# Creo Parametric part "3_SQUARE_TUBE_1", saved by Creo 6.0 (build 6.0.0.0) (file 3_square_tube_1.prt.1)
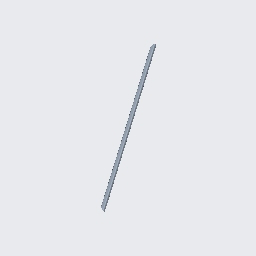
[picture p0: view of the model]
Units: Custom; MM, KILOGRAM, SECS
Materials in the file: STEEL

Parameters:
  BUW_NAME = "SQUARE TUBE"
  BUW_TYPE = "DIN EN 10219"
  BUW_SIZE = "25x25x3.0"
  BUW_LENGTH_STR = "1235"
  PTC_MATERIAL_NAME = "STEEL"
  BUW_PROFIL_TYPE = "square_tube"
  BUW_PROFILE_PATH = "parts//profiles/steel_beams_mm/"
  BUW_PROFILE_NAME_LANG = "SQUARE TUBE"
  BUW_TAB_SEL_INFO = "-2 TYPE DIN_EN_10219-1997 SIZE_DINEN_10219 25x25x3.0"
  NAMING = "SQUARE TUBE"
  DESIGNATION = "DIN EN 10219 25x25x3.0 x 1235"
  PROFIL_RASTER_POS = "X_0"
  BUW_OBJECT_ROLE = "PROFIL_SYSTEM_BORE_END_POINTS"
  PRO_UNIT_SYS = "Custom"

Other parameters: BUW_LENGTH, LENGTH, BUW_LENGTH_Z_MIN_PARAM, D8, D93, D94, d26, d8, d93, d94, d98, D98, SHEAR_MODULUS, THERM_EXPANSION_REF_TEMPERATURE, STRUCTURAL_DAMPING_COEFFICIENT, STRESS_LIMIT_FOR_TENSION, STRESS_LIMIT_FOR_COMPRESSION, STRESS_LIMIT_FOR_SHEAR, EMISSIVITY

Created from: SQUARE_TUBE.PRT

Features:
  1. datum plane "YZ"
  2. datum plane "XZ"
  3. datum plane "XY"
  4. coordinate system
  5. coordinate system
  6. coordinate system
  7. coordinate system
  8. datum plane "DTM3"
  9. datum plane "DTM4"
  10. datum plane "DTM5"
  11. protrusion
  12. round
  13. round
  14. datum axis
  15. datum point "PNT0"
  16. datum point

Other named items: PROFIL_CUT_QUILT, PROFILE_LENGTH_DIM, CONTACT_SURF_3, CONTACT_SURF_2, CONTACT_SURF_1, CONTACT_SURF_0, E, START_SURFACE, END_SURFACE, SIDE_SURF_3, SIDE_SURF_0, SIDE_SURF_1, SIDE_SURF_2, EDGE_7_S, EDGE_7_E, EDGE_1_S, EDGE_1_E, EDGE_3_S, EDGE_3_E, EDGE_5_S, EDGE_5_E, EDGE_6_S, EDGE_4_S, EDGE_2_S, EDGE_0_S, EDGE_6_E, EDGE_4_E, EDGE_2_E, EDGE_0_E, CS0, CS_S, CS_E, CS3

Named dimensions: X_ROT_S, Y_ROT_S, Z_OFF_S, X_ROT_E, Y_ROT_E, Z_OFF_E, PC_L, BUW_LENGTH_Z_MIN, BUW_LENGTH_DIM

Layers: 00_PROFIL_DATUM, 00_PROFIL_DRW_HIDE, 00_PROFIL_END_CSYS, 00_PROFIL_GEOMETRY, 00_PROFIL_QUILT, 00_PROFIL_SIZE_NOTE

Surfaces: 16 plane, 12 cylinder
